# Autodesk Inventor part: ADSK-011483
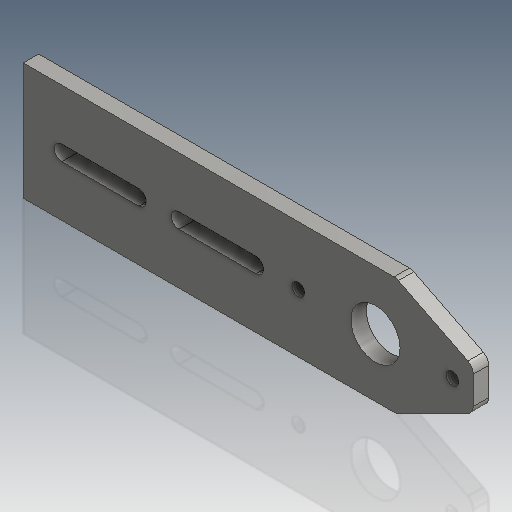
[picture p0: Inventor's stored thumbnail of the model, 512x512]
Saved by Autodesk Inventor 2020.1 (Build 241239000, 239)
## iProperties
Created: 1999-11
Part Number: ADSK-011483
Material: Pearson HRS
Document SubType Name: Modeling
Designer: mpflueger
Density: 7.83 g/cm^3
Appearance: Steel
Mass: 1477.12 g
Surface Area: 488.503 cm^2
Volume: 188.649 cm^3
Control State: 0
Master: False
Checked Out: False
Shininess: 25.0
Length Units: 11269
Angle Units: 11279
Time Units: 11290
Mass Units: 11283
Length Display Precision: 3
Angle Display Precision: 2
Compacted: True
Cutlength: 11.5
Material Desc: FLAT,HRS,0.375X03.000
Material_Number: A084408
Dimensions: 76x10x292 mm
Mass: 1,477 kg
VLT_Material: Pearson HRS
Density: 7.83
Volumn: 179.29325746960131
Area: 483.2710432365912
PropertySet Name: Model Information
Author: mpflueger
Revision Number: -
Title: ADSK-011483
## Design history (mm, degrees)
node "Solide1"
  node "Extrusion1" dims "d0" = 10, "d1" = 0
  node "Extrusion2" dims "d2" = 6.35, "d3" = 0
  node "Chamfer3" dims "d58" = 25, "d59" = 50, "d93" = 45 deg
  node "Chamfer4" dims "d60" = 50, "d61" = 25, "d94" = 45 deg
  node "Fillet2" dims "d68" = 6.35
  node "Hole5" dims "d74" = 8.376, "d75" = 9.525, "d76" = 6.35, "d77" = 60 deg, "d78" = 19.05, "d79" = 118 deg, "d95" = 20
sketch "Sketch1"
  geometry: L1 (-146, -38)-(146, -38); L2 (146, -38)-(146, 38); L3 (146, 38)-(-146, 38); L4 (-146, 38)-(-146, -38); 3 further points
  constraints: 8 end point, 2 midpoint, 2 parallel, 1 horizontal, 1 horizontal alignment, 1 perpendicular, 1 vertical alignment
  dimensions: "d56" = 76 distance of L1.end L2.end; "d84" = 292 distance of L1.start L1.end
sketch "Sketch2"
  geometry: L1 (146, 38)-(146, -38) reference; C1 r 16 at (82.5, 0); 1 further point
  constraints: 1 centre point, 1 horizontal alignment, 1 midpoint
  dimensions: "d24" = 63.5 distance from line of C1.centre L1; "d83" = 32 diameter of C1
sketch "Skizze14"
  geometry: L1 (-121, 0)-(-71, 0); L2 (-121, -5)-(-71, -5); L3 (-71, 5)-(-121, 5); L4 (-45, 0)-(5, 0); L5 (-45, -5)-(5, -5); L6 (5, 5)-(-45, 5); L7 (-146, -38)-(-146, 38) reference; A1 r 5 centre (-121, 0) between (-121, 5) and (-121, -5); A2 r 5 centre (-71, 0) between (-71, -5) and (-71, 5); A3 r 5 centre (-45, 0) between (-45, 5) and (-45, -5); A4 r 5 centre (5, 0) between (5, -5) and (5, 5); 4 further points
  constraints: 16 end point, 8 point on circle, 8 tangent, 4 centre point, 3 midpoint, 2 horizontal, 2 parallel, 1 collinear, 1 horizontal alignment
  dimensions: "d96" = 25 distance of point (-96, 0) L1.end; "d97" = 10 diameter of A2; "d98" = 25 distance of point (-20, 0) L4.end; "d99" = 10 diameter of A4; "d100" = 25 distance from line of L7 L1.start; "d101" = 76 distance of L4.start L1.start
extrude "Extrusion6" cut sketch "Skizze14" extent not by distance; stored distance "d102" = 0; taper "d103" = 0 deg
sketch "Sketch11"
  geometry: C1 r 16 at (82.5, 0) reference; 2 further points
  constraints: 2 horizontal alignment
  dimensions: "d72" = 50 distance of point (32.5, 0) C1.centre; "d73" = 50 distance of point (132.5, 0) C1.centre
node "Corps solides"
node "Corps surfaciques"
